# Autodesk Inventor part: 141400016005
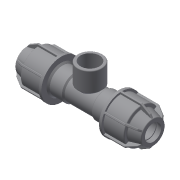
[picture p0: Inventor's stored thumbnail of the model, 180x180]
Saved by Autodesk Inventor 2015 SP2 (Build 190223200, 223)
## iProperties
Created: 2017-08
Part Number: 141400016005
Material: Generic
Description: PLASSON L.14 TEE FEMALE ADAPTOR (SILVER) 16 x 1/2" x 16
Document SubType Name: Modeling
Designer: KIM
Density: 1 g/cm^3
Appearance: Default
Author: KIM
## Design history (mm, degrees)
derived "141400.ipt"
feature "Solid1::141400.ipt"
feature "Solid2::141400.ipt"
tag "TaggingFeature1"
body "Solid1"
other parameters: "d1" = 16, "d2" = 51, "d4" = 15 deg, "d5" = 33.66, "d6" = 11.1078, "d10" = 39, "d16" = 16.32, "d17" = 2.55, "d22" = 25.6, "d24" = 2.55, "d25" = 35.1, "d26" = 29.25, "d27" = 2.55, "d28" = 135 deg, "d29" = 1.53, "d31" = 0.8, "d46" = 150 deg, "d49" = 1.95, "d50" = 0, "d58" = 0.48, "d61" = 360 deg, "d63" = 14.4, "d64" = 62, "d80" = 23.04, "d81" = 1.28, "d84" = 2.55, "d95" = 18.631, "d96" = 24.2203, "d97" = 19, "d98" = 14.4, "d99" = 16.95421, "d100" = 135 deg, "d108" = 0.8, "d111" = 0, "d_" = 16, "G_" = 18.631, "E_" = 39, "H_" = 124, "l_" = 51, "l_2" = 19
